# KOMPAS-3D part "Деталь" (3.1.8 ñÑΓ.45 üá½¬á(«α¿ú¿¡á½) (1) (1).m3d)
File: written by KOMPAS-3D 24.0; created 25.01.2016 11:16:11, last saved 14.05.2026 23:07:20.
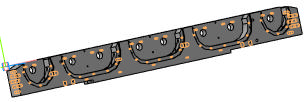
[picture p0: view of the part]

Document properties: Полное имя файла: E:\test_kompas\all_v22\3.1.8 дет.45 Балка(оригинал) (1) (1).m3d

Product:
- Part/product: Деталь
    Масса: 261.985445

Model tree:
1. Эскиз:1
2. Операция выдавливания:1
     Расстояние 1 = 115
3. Эскиз:9  (with: Грань.Операция выдавливания:1, Ребро.Операция выдавливания:1)
4. Вырезать элемент выдавливания:13
     Расстояние 1 = 115
5. Эскиз:19  (with: Грань.Операция выдавливания:1)
6. Вырезать элемент выдавливания:14
     Расстояние 1 = 231
7. Эскиз:20  (with: Грань.Операция выдавливания:1, Ребро.Операция выдавливания:1)
8. Эскиз:21  (with: Грань.Операция выдавливания:1)
9. Вырезать элемент выдавливания:15
     Расстояние 1 = 75
10. Вырезать элемент выдавливания:16
     Расстояние 1 = 10
11. Эскиз:22  (with: Грань.Операция выдавливания:1, Ребро.Операция выдавливания:1, Ребро.Вырезать элемент выдавливания:14)
12. Вырезать элемент выдавливания:17
     Расстояние 1 = 30
13. Эскиз:23  (with: Грань.Операция выдавливания:1)
14. Вырезать элемент выдавливания:18
     Расстояние 1 = 30
15. Условное изображение резьбы:1  (with: Ребро.Вырезать элемент выдавливания:17, Грань.Вырезать элемент выдавливания:17)
     Длина резьбы = 30; Шаг резьбы = 2; Номинальный диаметр резьбы = 20.0651
16. Условное изображение резьбы:2  (with: Ребро.Вырезать элемент выдавливания:17, Грань.Вырезать элемент выдавливания:17)
     Длина резьбы = 30; Шаг резьбы = 2; Номинальный диаметр резьбы = 20.0651
17. Условное изображение резьбы:3  (with: Ребро.Вырезать элемент выдавливания:18, Грань.Вырезать элемент выдавливания:18)
     Длина резьбы = 30; Шаг резьбы = 2; Номинальный диаметр резьбы = 20.0651
18. Условное изображение резьбы:4  (with: Ребро.Вырезать элемент выдавливания:18, Грань.Вырезать элемент выдавливания:18)
     Длина резьбы = 30; Шаг резьбы = 2; Номинальный диаметр резьбы = 20.0651
19. Эскиз:24  (with: Грань.Операция выдавливания:1)
20. Вырезать элемент выдавливания:19
     Расстояние 1 = 75
21. Эскиз:25  (with: Грань.Операция выдавливания:1, Ребро.Операция выдавливания:1)
22. Вырезать элемент выдавливания:20
     Расстояние 1 = 35
23. Условное изображение резьбы:5  (with: Ребро.Вырезать элемент выдавливания:20, Грань.Вырезать элемент выдавливания:20)
     Длина резьбы = 35; Шаг резьбы = 1.5; Номинальный диаметр резьбы = 20.0538
24. Условное изображение резьбы:6  (with: Ребро.Вырезать элемент выдавливания:20, Грань.Вырезать элемент выдавливания:20)
     Длина резьбы = 35; Шаг резьбы = 1.5; Номинальный диаметр резьбы = 20.0538
25. Условное изображение резьбы:7  (with: Ребро.Вырезать элемент выдавливания:20, Грань.Вырезать элемент выдавливания:20)
     Длина резьбы = 35; Шаг резьбы = 1.5; Номинальный диаметр резьбы = 20.0538
26. Условное изображение резьбы:8  (with: Ребро.Вырезать элемент выдавливания:20, Грань.Вырезать элемент выдавливания:20)
     Длина резьбы = 35; Шаг резьбы = 1.5; Номинальный диаметр резьбы = 20.0538
27. Условное изображение резьбы:9  (with: Ребро.Вырезать элемент выдавливания:20, Грань.Вырезать элемент выдавливания:20)
     Длина резьбы = 35; Шаг резьбы = 1; Номинальный диаметр резьбы = 19.5125
28. Условное изображение резьбы:10  (with: Ребро.Вырезать элемент выдавливания:20, Грань.Вырезать элемент выдавливания:20)
     Длина резьбы = 35; Шаг резьбы = 1; Номинальный диаметр резьбы = 19.5125
29. Эскиз:26  (with: Грань.Операция выдавливания:1, Ребро.Операция выдавливания:1, Ребро.Вырезать элемент выдавливания:13)
30. Вырезать элемент выдавливания:21
     Расстояние 1 = 35
31. Условное изображение резьбы:11  (with: Ребро.Вырезать элемент выдавливания:21, Грань.Вырезать элемент выдавливания:21)
     Длина резьбы = 35; Шаг резьбы = 1.5; Номинальный диаметр резьбы = 20.0538
32. Условное изображение резьбы:12  (with: Ребро.Вырезать элемент выдавливания:21, Грань.Вырезать элемент выдавливания:21)
     Длина резьбы = 35; Шаг резьбы = 1.5; Номинальный диаметр резьбы = 20.0538
33. Условное изображение резьбы:13  (with: Ребро.Вырезать элемент выдавливания:21, Грань.Вырезать элемент выдавливания:21)
     Длина резьбы = 35; Шаг резьбы = 1.5; Номинальный диаметр резьбы = 20.0538
34. Условное изображение резьбы:14  (with: Ребро.Вырезать элемент выдавливания:21, Грань.Вырезать элемент выдавливания:21)
     Длина резьбы = 35; Шаг резьбы = 1.5; Номинальный диаметр резьбы = 20.0538
35. Условное изображение резьбы:15  (with: Ребро.Вырезать элемент выдавливания:21, Грань.Вырезать элемент выдавливания:21)
     Длина резьбы = 35; Шаг резьбы = 1.5; Номинальный диаметр резьбы = 20.0538
36. Условное изображение резьбы:16  (with: Ребро.Вырезать элемент выдавливания:21, Грань.Вырезать элемент выдавливания:21)
     Длина резьбы = 35; Шаг резьбы = 1.5; Номинальный диаметр резьбы = 20.0538
37. Эскиз:27  (with: Грань.Операция выдавливания:1, Ребро.Операция выдавливания:1, Ребро.Вырезать элемент выдавливания:15)
38. Эскиз:28  (with: Грань.Операция выдавливания:1)
39. Вырезать элемент выдавливания:22
     Расстояние 1 = 115
40. Эскиз:29  (with: Грань.Вырезать элемент выдавливания:16, Ребро.Вырезать элемент выдавливания:16)
41. Вырезать элемент выдавливания:23
     Расстояние 1 = 13
42. Эскиз:30  (with: Грань.Вырезать элемент выдавливания:16)
43. Вырезать элемент выдавливания:24
     Расстояние 1 = 13
44. Условное изображение резьбы:17  (with: Ребро.Вырезать элемент выдавливания:23, Грань.Вырезать элемент выдавливания:23)
     Длина резьбы = 13; Шаг резьбы = 1; Номинальный диаметр резьбы = 9.51253
45. Условное изображение резьбы:18  (with: Ребро.Вырезать элемент выдавливания:23, Грань.Вырезать элемент выдавливания:23)
     Длина резьбы = 13; Шаг резьбы = 1; Номинальный диаметр резьбы = 9.51253
46. Условное изображение резьбы:19  (with: Ребро.Вырезать элемент выдавливания:23, Грань.Вырезать элемент выдавливания:23)
     Длина резьбы = 13; Шаг резьбы = 1; Номинальный диаметр резьбы = 9.51253
47. Условное изображение резьбы:20  (with: Ребро.Вырезать элемент выдавливания:23, Грань.Вырезать элемент выдавливания:23)
     Длина резьбы = 13; Шаг резьбы = 1; Номинальный диаметр резьбы = 9.51253
48. Условное изображение резьбы:21  (with: Ребро.Вырезать элемент выдавливания:23, Грань.Вырезать элемент выдавливания:23)
     Длина резьбы = 13; Шаг резьбы = 1; Номинальный диаметр резьбы = 9.51253
49. Условное изображение резьбы:22  (with: Ребро.Вырезать элемент выдавливания:24, Грань.Вырезать элемент выдавливания:24)
     Длина резьбы = 13; Шаг резьбы = 1; Номинальный диаметр резьбы = 9.51253
50. Условное изображение резьбы:23  (with: Ребро.Вырезать элемент выдавливания:24, Грань.Вырезать элемент выдавливания:24)
     Длина резьбы = 13; Шаг резьбы = 1; Номинальный диаметр резьбы = 9.51253
51. Условное изображение резьбы:24  (with: Ребро.Вырезать элемент выдавливания:24, Грань.Вырезать элемент выдавливания:24)
     Длина резьбы = 13; Шаг резьбы = 1; Номинальный диаметр резьбы = 9.51253
52. Условное изображение резьбы:25  (with: Ребро.Вырезать элемент выдавливания:24, Грань.Вырезать элемент выдавливания:24)
     Длина резьбы = 13; Шаг резьбы = 1; Номинальный диаметр резьбы = 9.51253
53. Условное изображение резьбы:26  (with: Ребро.Вырезать элемент выдавливания:24, Грань.Вырезать элемент выдавливания:24)
     Длина резьбы = 13; Шаг резьбы = 1; Номинальный диаметр резьбы = 9.51253
54. Эскиз:31  (with: Грань.Вырезать элемент выдавливания:16, Ребро.Вырезать элемент выдавливания:16, Ребро.Вырезать элемент выдавливания:19)
55. Вырезать элемент выдавливания:25
     Расстояние 1 = 13
56. Условное изображение резьбы:27  (with: Ребро.Вырезать элемент выдавливания:25, Грань.Вырезать элемент выдавливания:25)
     Длина резьбы = 13; Шаг резьбы = 1; Номинальный диаметр резьбы = 9.51253
57. Условное изображение резьбы:28  (with: Ребро.Вырезать элемент выдавливания:25, Грань.Вырезать элемент выдавливания:25)
     Длина резьбы = 13; Шаг резьбы = 1; Номинальный диаметр резьбы = 9.51253
58. Условное изображение резьбы:29  (with: Ребро.Вырезать элемент выдавливания:25, Грань.Вырезать элемент выдавливания:25)
     Длина резьбы = 13; Шаг резьбы = 1; Номинальный диаметр резьбы = 9.51253
59. Условное изображение резьбы:30  (with: Ребро.Вырезать элемент выдавливания:25, Грань.Вырезать элемент выдавливания:25)
     Длина резьбы = 13; Шаг резьбы = 1; Номинальный диаметр резьбы = 9.51253
60. Условное изображение резьбы:31  (with: Ребро.Вырезать элемент выдавливания:25, Грань.Вырезать элемент выдавливания:25)
     Длина резьбы = 13; Шаг резьбы = 1; Номинальный диаметр резьбы = 9.51253
61. Условное изображение резьбы:32  (with: Ребро.Вырезать элемент выдавливания:25, Грань.Вырезать элемент выдавливания:25)
     Длина резьбы = 13; Шаг резьбы = 1; Номинальный диаметр резьбы = 9.51253
62. Условное изображение резьбы:33  (with: Ребро.Вырезать элемент выдавливания:25, Грань.Вырезать элемент выдавливания:25)
     Длина резьбы = 13; Шаг резьбы = 1; Номинальный диаметр резьбы = 9.51253
63. Эскиз:32  (with: Грань.Вырезать элемент выдавливания:16)
64. Вырезать элемент выдавливания:26
     Расстояние 1 = 13
65. Условное изображение резьбы:34  (with: Ребро.Вырезать элемент выдавливания:26, Грань.Вырезать элемент выдавливания:26)
     Длина резьбы = 13; Шаг резьбы = 1; Номинальный диаметр резьбы = 9.51253
66. Условное изображение резьбы:35  (with: Ребро.Вырезать элемент выдавливания:26, Грань.Вырезать элемент выдавливания:26)
     Длина резьбы = 13; Шаг резьбы = 1; Номинальный диаметр резьбы = 9.51253
67. Условное изображение резьбы:36  (with: Ребро.Вырезать элемент выдавливания:26, Грань.Вырезать элемент выдавливания:26)
     Длина резьбы = 13; Шаг резьбы = 1; Номинальный диаметр резьбы = 9.51253
68. Условное изображение резьбы:37  (with: Ребро.Вырезать элемент выдавливания:26, Грань.Вырезать элемент выдавливания:26)
     Длина резьбы = 13; Шаг резьбы = 1; Номинальный диаметр резьбы = 9.51253
69. Условное изображение резьбы:38  (with: Ребро.Вырезать элемент выдавливания:26, Грань.Вырезать элемент выдавливания:26)
     Длина резьбы = 13; Шаг резьбы = 1; Номинальный диаметр резьбы = 9.51253
70. Условное изображение резьбы:39  (with: Ребро.Вырезать элемент выдавливания:26, Грань.Вырезать элемент выдавливания:26)
     Длина резьбы = 13; Шаг резьбы = 1; Номинальный диаметр резьбы = 9.51253
71. Условное изображение резьбы:40  (with: Ребро.Вырезать элемент выдавливания:26, Грань.Вырезать элемент выдавливания:26)
     Длина резьбы = 13; Шаг резьбы = 1; Номинальный диаметр резьбы = 9.51253
72. Эскиз:33  (with: Грань.Вырезать элемент выдавливания:16, Ребро.Вырезать элемент выдавливания:16)
73. Вырезать элемент выдавливания:27
     Расстояние 1 = 13
74. Условное изображение резьбы:41  (with: Ребро.Вырезать элемент выдавливания:27, Грань.Вырезать элемент выдавливания:27)
     Длина резьбы = 13; Шаг резьбы = 1; Номинальный диаметр резьбы = 9.51253
75. Условное изображение резьбы:42  (with: Ребро.Вырезать элемент выдавливания:27, Грань.Вырезать элемент выдавливания:27)
     Длина резьбы = 13; Шаг резьбы = 1; Номинальный диаметр резьбы = 9.51253
76. Условное изображение резьбы:43  (with: Ребро.Вырезать элемент выдавливания:27, Грань.Вырезать элемент выдавливания:27)
     Длина резьбы = 13; Шаг резьбы = 1; Номинальный диаметр резьбы = 9.51253
77. Условное изображение резьбы:44  (with: Ребро.Вырезать элемент выдавливания:27, Грань.Вырезать элемент выдавливания:27)
     Длина резьбы = 13; Шаг резьбы = 1; Номинальный диаметр резьбы = 9.51253
78. Условное изображение резьбы:45  (with: Ребро.Вырезать элемент выдавливания:27, Грань.Вырезать элемент выдавливания:27)
     Длина резьбы = 13; Шаг резьбы = 1; Номинальный диаметр резьбы = 9.51253
79. Условное изображение резьбы:46  (with: Ребро.Вырезать элемент выдавливания:27, Грань.Вырезать элемент выдавливания:27)
     Длина резьбы = 13; Шаг резьбы = 1; Номинальный диаметр резьбы = 9.51253
80. Условное изображение резьбы:47  (with: Ребро.Вырезать элемент выдавливания:27, Грань.Вырезать элемент выдавливания:27)
     Длина резьбы = 13; Шаг резьбы = 1; Номинальный диаметр резьбы = 9.51253
81. Эскиз:34  (with: Грань.Операция выдавливания:1, Ребро.Операция выдавливания:1)
82. Эскиз:35  (with: Грань.Операция выдавливания:1, Ребро.Операция выдавливания:1, Ребро.Вырезать элемент выдавливания:17)
83. Вырезать элемент выдавливания:28
     Расстояние 1 = 94
84. Эскиз:36  (with: Грань.Операция выдавливания:1, Ребро.Операция выдавливания:1)
85. Вырезать элемент выдавливания:29
     Расстояние 1 = 21
86. Эскиз:37  (with: Грань.Вырезать элемент выдавливания:15, Ребро.Вырезать элемент выдавливания:15)
87. Вырезать элемент выдавливания:30
     Расстояние 1 = 40
88. Эскиз:38  (with: Грань.Операция выдавливания:1, Ребро.Операция выдавливания:1)
89. Вырезать элемент выдавливания:31
     Расстояние 1 = 10
90. Эскиз:39  (with: Грань.Операция выдавливания:1, Ребро.Операция выдавливания:1)
91. Вырезать элемент выдавливания:32
     Расстояние 1 = 50
92. Условное изображение резьбы:48  (with: Ребро.Вырезать элемент выдавливания:32, Грань.Вырезать элемент выдавливания:32)
     Длина резьбы = 50; Шаг резьбы = 1; Номинальный диаметр резьбы = 18.0325
93. Условное изображение резьбы:49  (with: Ребро.Вырезать элемент выдавливания:32, Грань.Вырезать элемент выдавливания:32)
     Длина резьбы = 50; Шаг резьбы = 1; Номинальный диаметр резьбы = 18.0325
94. Условное изображение резьбы:50  (with: Ребро.Вырезать элемент выдавливания:32, Грань.Вырезать элемент выдавливания:32)
     Длина резьбы = 50; Шаг резьбы = 1; Номинальный диаметр резьбы = 18.0325
95. Условное изображение резьбы:51  (with: Ребро.Вырезать элемент выдавливания:32, Грань.Вырезать элемент выдавливания:32)
     Длина резьбы = 50; Шаг резьбы = 1; Номинальный диаметр резьбы = 18.0325
96. Эскиз:40  (with: Грань.Операция выдавливания:1, Ребро.Операция выдавливания:1, Ребро.Вырезать элемент выдавливания:13, Ребро.Вырезать элемент выдавливания:22, Ребро.Вырезать элемент выдавливания:29)
97. Вырезать элемент выдавливания:33
     Расстояние 1 = 70
98. Условное изображение резьбы:52  (with: Ребро.Вырезать элемент выдавливания:33, Грань.Вырезать элемент выдавливания:33)
     Длина резьбы = 70; Шаг резьбы = 1; Номинальный диаметр резьбы = 28.0325
99. Условное изображение резьбы:53  (with: Ребро.Вырезать элемент выдавливания:33, Грань.Вырезать элемент выдавливания:33)
     Длина резьбы = 70; Шаг резьбы = 1; Номинальный диаметр резьбы = 28.0325
100. Эскиз:41  (with: Грань.Операция выдавливания:1)
101. Вырезать элемент выдавливания:34
     Расстояние 1 = 30
102. Условное изображение резьбы:54  (with: Ребро.Вырезать элемент выдавливания:34, Грань.Вырезать элемент выдавливания:34)
     Длина резьбы = 30; Шаг резьбы = 1; Номинальный диаметр резьбы = 8.03253
103. Условное изображение резьбы:55  (with: Ребро.Вырезать элемент выдавливания:34, Грань.Вырезать элемент выдавливания:34)
     Длина резьбы = 30; Шаг резьбы = 1; Номинальный диаметр резьбы = 8.03253
104. Условное изображение резьбы:56  (with: Ребро.Вырезать элемент выдавливания:34, Грань.Вырезать элемент выдавливания:34)
     Длина резьбы = 30; Шаг резьбы = 1; Номинальный диаметр резьбы = 8.03253
105. Условное изображение резьбы:57  (with: Ребро.Вырезать элемент выдавливания:34, Грань.Вырезать элемент выдавливания:34)
     Длина резьбы = 30; Шаг резьбы = 1; Номинальный диаметр резьбы = 8.03253
106. Условное изображение резьбы:58  (with: Ребро.Вырезать элемент выдавливания:34, Грань.Вырезать элемент выдавливания:34)
     Длина резьбы = 30; Шаг резьбы = 1; Номинальный диаметр резьбы = 8.03253
107. Вырезать элемент выдавливания:35
     Расстояние 1 = 10
108. Эскиз:42  (with: Грань.Операция выдавливания:1, Ребро.Вырезать элемент выдавливания:33)
109. Вырезать элемент выдавливания:36
     Расстояние 1 = 55
110. Условное изображение резьбы:59  (with: Ребро.Вырезать элемент выдавливания:36, Грань.Вырезать элемент выдавливания:36)
     Длина резьбы = 55; Шаг резьбы = 1; Номинальный диаметр резьбы = 16.0325
111. Эскиз:43  (with: Грань.Операция выдавливания:1, Ребро.Операция выдавливания:1, Ребро.Вырезать элемент выдавливания:22)
112. Вырезать элемент выдавливания:37
     Расстояние 1 = 30
113. Условное изображение резьбы:60  (with: Ребро.Вырезать элемент выдавливания:37, Грань.Вырезать элемент выдавливания:37)
     Длина резьбы = 30; Шаг резьбы = 1; Номинальный диаметр резьбы = 11.0325
114. Условное изображение резьбы:61  (with: Ребро.Вырезать элемент выдавливания:37, Грань.Вырезать элемент выдавливания:37)
     Длина резьбы = 30; Шаг резьбы = 1; Номинальный диаметр резьбы = 11.0325
115. Условное изображение резьбы:62  (with: Ребро.Вырезать элемент выдавливания:37, Грань.Вырезать элемент выдавливания:37)
     Длина резьбы = 30; Шаг резьбы = 1; Номинальный диаметр резьбы = 11.0325
116. Условное изображение резьбы:63  (with: Ребро.Вырезать элемент выдавливания:37, Грань.Вырезать элемент выдавливания:37)
     Длина резьбы = 30; Шаг резьбы = 1; Номинальный диаметр резьбы = 11.0325
117. Условное изображение резьбы:64  (with: Ребро.Вырезать элемент выдавливания:37, Грань.Вырезать элемент выдавливания:37)
     Длина резьбы = 30; Шаг резьбы = 1; Номинальный диаметр резьбы = 11.0325
118. Условное изображение резьбы:65  (with: Ребро.Вырезать элемент выдавливания:37, Грань.Вырезать элемент выдавливания:37)
     Длина резьбы = 30; Шаг резьбы = 1; Номинальный диаметр резьбы = 11.0325
119. Условное изображение резьбы:66  (with: Ребро.Вырезать элемент выдавливания:37, Грань.Вырезать элемент выдавливания:37)
     Длина резьбы = 30; Шаг резьбы = 1; Номинальный диаметр резьбы = 11.0325
120. Условное изображение резьбы:67  (with: Ребро.Вырезать элемент выдавливания:37, Грань.Вырезать элемент выдавливания:37)
     Длина резьбы = 30; Шаг резьбы = 1; Номинальный диаметр резьбы = 11.0325
121. Условное изображение резьбы:68  (with: Ребро.Вырезать элемент выдавливания:37, Грань.Вырезать элемент выдавливания:37)
     Длина резьбы = 30; Шаг резьбы = 1; Номинальный диаметр резьбы = 11.0325
122. Условное изображение резьбы:69  (with: Ребро.Вырезать элемент выдавливания:37, Грань.Вырезать элемент выдавливания:37)
     Длина резьбы = 30; Шаг резьбы = 1; Номинальный диаметр резьбы = 11.0325
123. Условное изображение резьбы:70  (with: Ребро.Вырезать элемент выдавливания:37, Грань.Вырезать элемент выдавливания:37)
     Длина резьбы = 30; Шаг резьбы = 1; Номинальный диаметр резьбы = 11.0325
124. Условное изображение резьбы:71  (with: Ребро.Вырезать элемент выдавливания:37, Грань.Вырезать элемент выдавливания:37)
     Длина резьбы = 30; Шаг резьбы = 1; Номинальный диаметр резьбы = 11.0325
125. Условное изображение резьбы:72  (with: Ребро.Вырезать элемент выдавливания:37, Грань.Вырезать элемент выдавливания:37)
     Длина резьбы = 30; Шаг резьбы = 1; Номинальный диаметр резьбы = 11.0325
126. Условное изображение резьбы:73  (with: Ребро.Вырезать элемент выдавливания:37, Грань.Вырезать элемент выдавливания:37)
     Длина резьбы = 30; Шаг резьбы = 1; Номинальный диаметр резьбы = 11.0325
127. Условное изображение резьбы:74  (with: Ребро.Вырезать элемент выдавливания:37, Грань.Вырезать элемент выдавливания:37)
     Длина резьбы = 30; Шаг резьбы = 1; Номинальный диаметр резьбы = 11.0325
128. Условное изображение резьбы:75  (with: Ребро.Вырезать элемент выдавливания:37, Грань.Вырезать элемент выдавливания:37)  (labels: 4061045924-6285-0-0|0)
     Длина резьбы = 30; Шаг резьбы = 1; Номинальный диаметр резьбы = 11.0325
